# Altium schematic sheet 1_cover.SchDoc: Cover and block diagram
size A4; ENG_APP_DATE: --/--/--; DSN_APP_DATE: --/--/--; CHK_APP_DATE: --/--/--; OrganizationName: Pluton UPV; Address1: Universitat Politècnica; Address2: de València (UPV); Address3: Camí de Vera, València; Address4: Spain; DocumentNumber: 1; Revision: 0; SheetNumber: 1; SheetTotal: 8
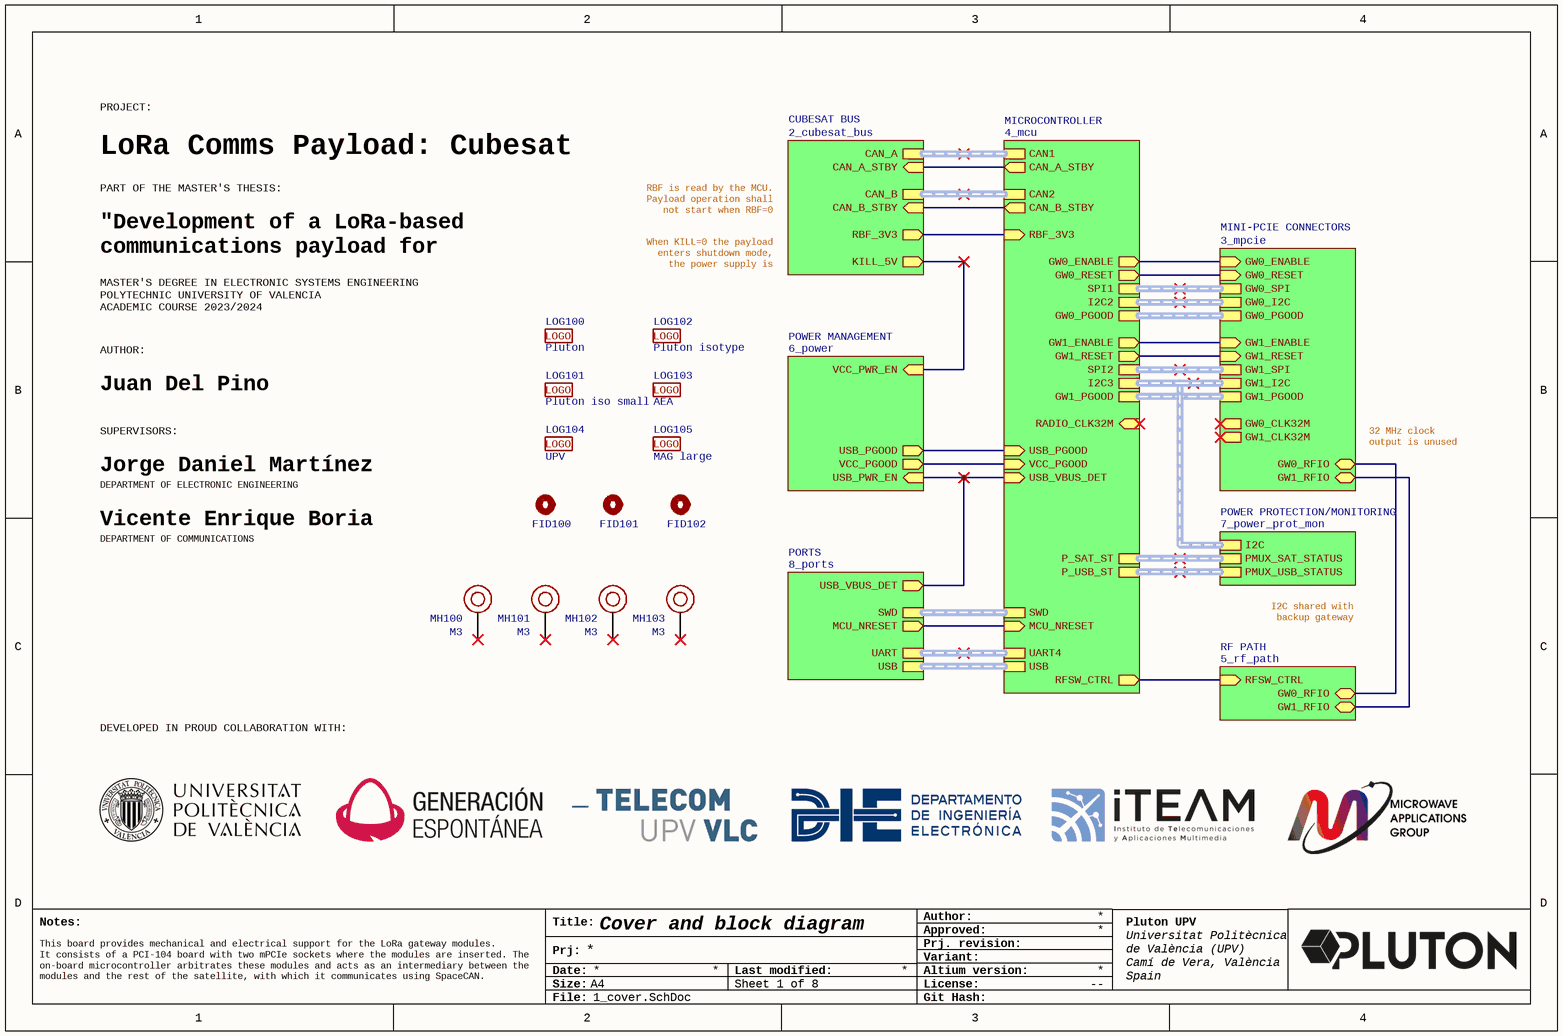
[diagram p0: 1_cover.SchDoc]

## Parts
FID100  Fiducial Mark  [Fiducial_1_3_mm]  (value not drawn)  (no BOM)
FID101  Fiducial Mark  [Fiducial_1_3_mm]  (value not drawn)  (no BOM)
FID102  Fiducial Mark  [Fiducial_1_3_mm]  (value not drawn)  (no BOM)
LOG100  Pluton  [logo_pluton]  (no BOM)
LOG101  Pluton iso small  [logo_pluton_isotype_small]  (no BOM)
LOG102  Pluton isotype  [logo_pluton_isotype]  (no BOM)
LOG103  AEA  [logo_aea]  (no BOM)
LOG104  UPV  [logo_upv]  (no BOM)
LOG105  MAG large  [logo_mag_big]  (no BOM)
MH100  M3  [MH Cubesat M3]  (no BOM)
MH101  M3  [MH Cubesat M3]  (no BOM)
MH102  M3  [MH Cubesat M3]  (no BOM)
MH103  M3  [MH Cubesat M3]  (no BOM)

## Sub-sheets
CUBESAT BUS = 2_cubesat_bus: CAN_A (harness CAN), CAN_B (harness CAN), CAN_A_STBY (in), CAN_B_STBY (in), KILL_5V (out), RBF_3V3 (out)
MICROCONTROLLER = 4_mcu: SWD (harness SWD), USB (harness USB), RADIO_CLK32M (in), MCU_NRESET (in), GW1_RESET (out), GW0_RESET (out), GW0_ENABLE (out), GW1_ENABLE (out), GW0_PGOOD (harness PGOOD), GW1_PGOOD (harness PGOOD), RBF_3V3 (in), VCC_PGOOD (in), SPI1 (harness SPI), SPI2 (harness SPI), CAN1 (harness CAN), CAN2 (harness CAN), I2C3 (harness I2C), I2C2 (harness I2C), UART4 (harness UART), CAN_B_STBY (out), CAN_A_STBY (out), RFSW_CTRL (out), USB_PGOOD (in), USB_VBUS_DET (in), P_SAT_ST (harness PMUX_STATUS), P_USB_ST (harness PMUX_STATUS)
MINI-PCIE CONNECTORS = 3_mpcie: GW0_RESET (in), GW0_ENABLE (in), GW0_CLK32M (out), GW1_RESET (in), GW1_ENABLE (in), GW1_CLK32M (out), GW0_SPI (harness SPI), GW0_PGOOD (harness PGOOD), GW1_SPI (harness SPI), GW0_I2C (harness I2C), GW1_PGOOD (harness PGOOD), GW1_I2C (harness I2C), GW0_RFIO (bidir), GW1_RFIO (bidir)
PORTS = 8_ports: SWD (harness SWD), MCU_NRESET (out), UART (harness UART), USB (harness USB), USB_VBUS_DET (out)
POWER MANAGEMENT = 6_power: VCC_PWR_EN (in), VCC_PGOOD (out), USB_PGOOD (out), USB_PWR_EN (in)
POWER PROTECTION/MONITORING = 7_power_prot_mon: I2C (harness I2C), PMUX_SAT_STATUS (harness PMUX_STATUS), PMUX_USB_STATUS (harness PMUX_STATUS)
RF PATH = 5_rf_path: RFSW_CTRL (in), GW0_RFIO (bidir), GW1_RFIO (bidir)

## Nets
(unnamed): sheet CUBESAT BUS/CAN_A_STBY, sheet MICROCONTROLLER/CAN_A_STBY
(unnamed): sheet CUBESAT BUS/CAN_B_STBY, sheet MICROCONTROLLER/CAN_B_STBY  [a separate net that carries the same name]
(unnamed): sheet CUBESAT BUS/KILL_5V, sheet POWER MANAGEMENT/VCC_PWR_EN  [a separate net that carries the same name]
(unnamed): sheet CUBESAT BUS/RBF_3V3, sheet MICROCONTROLLER/RBF_3V3  [a separate net that carries the same name]
(unnamed): sheet RF PATH/RFSW_CTRL, sheet MICROCONTROLLER/RFSW_CTRL  [a separate net that carries the same name]
(unnamed): sheet RF PATH/GW0_RFIO, sheet MINI-PCIE CONNECTORS/GW0_RFIO  [a separate net that carries the same name]
(unnamed): sheet RF PATH/GW1_RFIO, sheet MINI-PCIE CONNECTORS/GW1_RFIO  [a separate net that carries the same name]
(unnamed): sheet MINI-PCIE CONNECTORS/GW0_RESET, sheet MICROCONTROLLER/GW0_RESET  [a separate net that carries the same name]
(unnamed): sheet MINI-PCIE CONNECTORS/GW0_ENABLE, sheet MICROCONTROLLER/GW0_ENABLE  [a separate net that carries the same name]
(unnamed): sheet MINI-PCIE CONNECTORS/GW1_RESET, sheet MICROCONTROLLER/GW1_RESET  [a separate net that carries the same name]
(unnamed): sheet MINI-PCIE CONNECTORS/GW1_ENABLE, sheet MICROCONTROLLER/GW1_ENABLE  [a separate net that carries the same name]
(unnamed): sheet POWER MANAGEMENT/VCC_PGOOD, sheet MICROCONTROLLER/VCC_PGOOD  [a separate net that carries the same name]
(unnamed): sheet POWER MANAGEMENT/USB_PGOOD, sheet MICROCONTROLLER/USB_PGOOD  [a separate net that carries the same name]
(unnamed): sheet POWER MANAGEMENT/USB_PWR_EN, sheet MICROCONTROLLER/USB_VBUS_DET, sheet PORTS/USB_VBUS_DET  [a separate net that carries the same name]
(unnamed): sheet MICROCONTROLLER/MCU_NRESET, sheet PORTS/MCU_NRESET  [a separate net that carries the same name]

Not connected (* = marked no-connect by the designer): MH100 1*; MH101 1*; MH102 1*; MH103 1*

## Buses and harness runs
harness sheet CUBESAT BUS/CAN_A = sheet MICROCONTROLLER/CAN1
harness sheet CUBESAT BUS/CAN_B = sheet MICROCONTROLLER/CAN2
harness sheet MICROCONTROLLER/GW0_PGOOD = sheet MINI-PCIE CONNECTORS/GW0_PGOOD
harness sheet MICROCONTROLLER/GW1_PGOOD = sheet MINI-PCIE CONNECTORS/GW1_PGOOD
harness sheet MICROCONTROLLER/I2C2 = sheet MINI-PCIE CONNECTORS/GW0_I2C
harness sheet MICROCONTROLLER/I2C3 = sheet MINI-PCIE CONNECTORS/GW1_I2C = sheet POWER PROTECTION/MONITORING/I2C
harness sheet MICROCONTROLLER/P_SAT_ST = sheet POWER PROTECTION/MONITORING/PMUX_SAT_STATUS
harness sheet MICROCONTROLLER/P_USB_ST = sheet POWER PROTECTION/MONITORING/PMUX_USB_STATUS
harness sheet MICROCONTROLLER/SPI1 = sheet MINI-PCIE CONNECTORS/GW0_SPI
harness sheet MICROCONTROLLER/SPI2 = sheet MINI-PCIE CONNECTORS/GW1_SPI
harness sheet MICROCONTROLLER/SWD = sheet PORTS/SWD
harness sheet MICROCONTROLLER/UART4 = sheet PORTS/UART
harness sheet MICROCONTROLLER/USB = sheet PORTS/USB

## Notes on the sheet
- PROJECT:
- LoRa Comms Payload: Cubesat Carrier
- PART OF THE MASTER'S THESIS:
- RBF is read by the MCU. Payload operation shall not start when RBF=0
- (near LOG100) MASTER'S DEGREE IN ELECTRONIC SYSTEMS ENGINEERING
  POLYTECHNIC UNIVERSITY OF VALENCIA
  ACADEMIC COURSE 2023/2024
- "Development of a LoRa-based communications payload for CubeSat"
- When KILL=0 the payload enters shutdown mode, the power supply is disabled.
- AUTHOR:
- Juan Del Pino Mena
- SUPERVISORS:
- 32 MHz clock output is unused
- Jorge Daniel Martínez Pérez
- Vicente Boria Esbert
- DEPARTMENT OF ELECTRONIC ENGINEERING
- Vicente Enrique Boria Esbert
- DEPARTMENT OF COMMUNICATIONS
- I2C shared with backup gateway
- DEVELOPED IN PROUD COLLABORATION WITH:
- This board provides mechanical and electrical support for the LoRa gateway modules.
  It consists of a PCI-104 board with two mPCIe sockets where the modules are inserted. The on-board microcontroller arbitrates these modules and acts as an intermediary between the modules and the rest of the satellite, with which it communicates using SpaceCAN.

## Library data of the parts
FID100-FID102 = Fiducial Mark: FIducial Mark (concentric 1 mm, 3 mm)
LOG100-LOG105 = Logo
MH100-MH103 = MH M3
